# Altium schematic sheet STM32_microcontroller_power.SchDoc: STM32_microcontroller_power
size A4; Date: Not used; ApprovedBy: Not used; CheckedBy: Not used; Author: Not used; CompanyName: STMicroelectronics; DrawnBy: Not used; Engineer: Not used; Organization: Not used; Address1: Not used; Address2: Not used; Address3: Not used; Address4: Not used; DocumentNumber: Not used; Revision: Not used; SheetNumber: 4; SheetTotal: 12
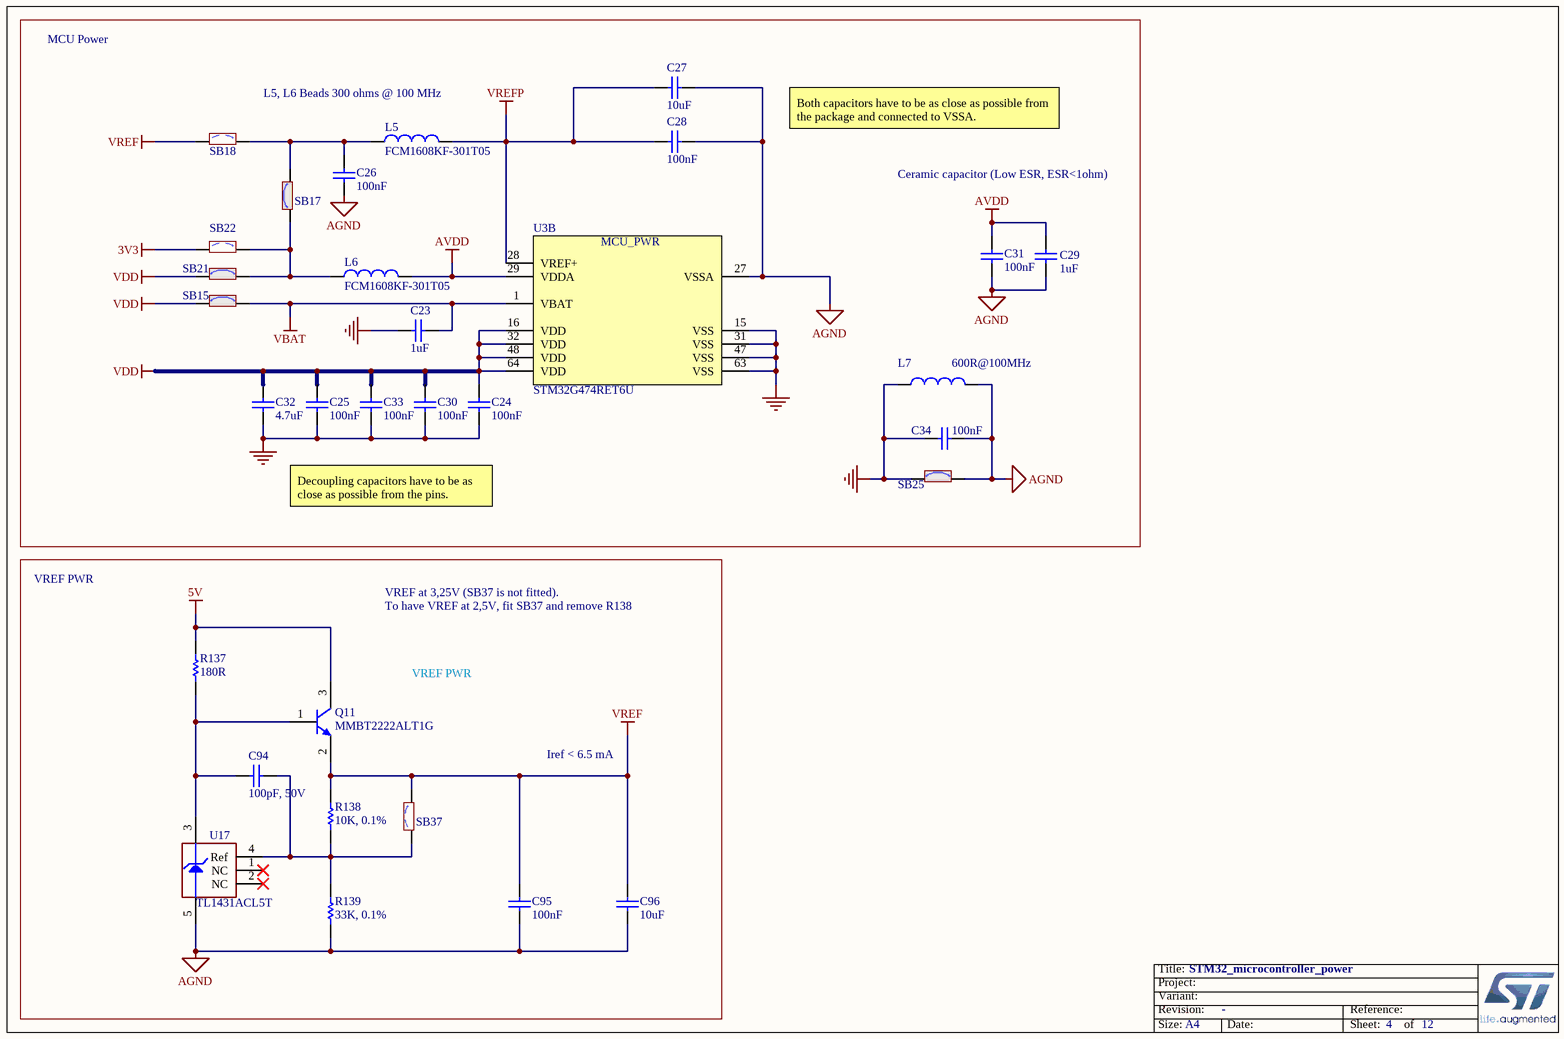
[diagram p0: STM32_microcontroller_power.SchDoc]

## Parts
C23  value 1uF  [C0603]
C24  value 100nF  [C0402]
C25  value 100nF  [C0402]
C26  value 100nF  [C0402]
C27  value 10uF  [C0603]
C28  value 100nF  [C0402]
C29  value 1uF  [C0603]
C30  value 100nF  [C0402]
C31  value 100nF  [C0402]
C32  value 4.7uF  [C0603]
C33  value 100nF  [C0402]
C34  value 100nF  [C0402]
C94  value 100pF, 50V  [C0603_H0P8]
C95  value 100nF  [C0603]
C96  value 10uF  [C0603]
L5  value FCM1608KF-301T05  [L0603]  (hidden comment: BEAD)
L6  value FCM1608KF-301T05  [L0603]  (hidden comment: BEAD)
L7  value 600R@100MHz  [L0603]
Q11  value MMBT2222ALT1G  [NPN_SOT23]  (hidden comment: 9013-SOT23)
R137  value 180R  [R0603]
R138  value 10K, 0.1%  [R0603]
R139  value 33K, 0.1%  [R0603]
SB15  (no value)  [SOLDER-BRIDGE_R0603-0R]
SB17  (no value)  [SOLDER-BRIDGE_R0603-0R]
SB18  (no value)  [SOLDER-BRIDGE_R0603-0R]
SB21  (no value)  [SOLDER-BRIDGE_R0603-0R]
SB22  (no value)  [SOLDER-BRIDGE_R0603-0R]
SB25  (no value)  [SOLDER-BRIDGE_R0603-0R]
SB37  (no value)  [SOLDER-BRIDGE_R0603-0R]
U3  STM32G474RET6U  [ICC_LQFP64_10X10_P050]  (part B of 2)
U17  value TL1431ACL5T  [ICC_SOT23-5L_H1P45]

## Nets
3V3: SB22.1
5V: Q11.3(C) R137.2
AGND: C26.1 C27.1 C28.2 C29.1 C31.1 C34.2 C95.1 C96.1 L7.2 R139.1 SB25.2 U3.27(VSSA) U17.5(Anode)
AVDD: C29.2 C31.2 L6.2 U3.29(VDDA)
GND: C23.1 C24.1 C25.1 C30.1 C32.1 C33.1 C34.1 L7.1 SB25.1 U3.15(VSS) U3.31(VSS) U3.47(VSS) U3.63(VSS)
VBAT: C23.2 SB15.2 U3.1(VBAT)
VDD: C24.2 C25.2 C30.2 C32.2 C33.2 SB15.1 SB21.1 U3.16(VDD) U3.32(VDD) U3.48(VDD) U3.64(VDD)
VREF: C95.2 C96.2 Q11.2(E) R138.2 SB18.1 SB37.2
VREFP: C27.2 C28.1 L5.2 U3.28(VREF+)
NetC26_2: C26.2 L5.1 SB17.2 SB18.2
NetC94_1: C94.1 Q11.1(B) R137.1 U17.3(Cathode)
NetC94_2: C94.2 R138.1 R139.2 SB37.1 U17.4(Ref)
NetL6_1: L6.1 SB17.1 SB21.2 SB22.2

Not connected (* = marked no-connect by the designer): U17 1(NC)* 2(NC)*

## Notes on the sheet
- MCU Power
- L5, L6 Beads 300 ohms @ 100 MHz
- Both capacitors have to be as close as possible from the package and connected to VSSA.
- Ceramic capacitor (Low ESR, ESR<1ohm)
- Decoupling capacitors have to be as close as possible from the pins.
- VREF PWR
- VREF at 3,25V (SB37 is not fitted).
- To have VREF at 2,5V, fit SB37 and remove R138
- Iref < 6.5 mA

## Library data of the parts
C23 C29 = MCD-00010: Capacitor, MLCC, 1uF, 16V, X5R, 10%, 0603, T=0,8mm; Manufacturer_Part_Number: CC0603KRX5R7BB105; Manufacturer: YAGEO; Provided_By: SUBCO
C24-C26 C28 C30 C31 C33 C34 = MCD-00102: Capacitor, MLCC, 100nF, 16V, X7R, 10%, 0402, T=0,5mm; Manufacturer_Part_Number: CC0402KRX7R7BB104; Manufacturer: YAGEO; Alternate_Manufacturer_Part_Number: GCM155R71C104KA55D; Alternate_Manufacturer: MURATA; Provided_By: SUBCO
C27 C96 = MCD-01124: Capacitor, MLCC, 10µF, 10V, X5R, 10%, 0603, T=0.8mm; Manufacturer_Part_Number: GRM188R61A106KAAL; Manufacturer: MURATA; Provided_By: SUBCO
C32 = MCD-00009: Capacitor, MLCC, 4.7uF, 16V, X5R, 10%, 0603, T=0.8mm; Manufacturer_Part_Number: CC0603KRX5R7BB475; Manufacturer: YAGEO; Provided_By: SUBCO
C94 = MCD-01648: Capacitor, MLCC, 100pF, 50V, NPO, 5%, 0603, T=0,8mm; Manufacturer_Part_Number: CC0603JRNPO9BN101; Manufacturer: YAGEO; Provided_By: SUBCO
C95 = MCD-00211: Capacitor, MLCC, 100nF, 16V, X7R, 10%, 0603, T=0,8mm; Manufacturer_Part_Number: CC0603KRX7R7BB104; Manufacturer: YAGEO; Provided_By: SUBCO
L5 L6 = MCD-01735: Bead,300R,500mA,0603; Part_Type: Inductor; Manufacturer: TAI-TECH; Provided_By: SUBCO
L7 = MCD-00047: SMD Chip ferrite bead, 600R@100MHz +/-25%, 350mA, 500mohm DC, 0603, T=0.8mm; Part_Type: Inductor; Manufacturer_Part_Number: FCM1608KF-601T03; Manufacturer: TAI-TECH; Provided_By: SUBCO
Q11 = MCD-01737: NPN Bipolar Transistor; Part_Type: IC; Manufacturer: ON SEMICONDUCTOR; Provided_By: SUBCO
R137 = MCD-00342: Resistor,180R,0603,1%,1/10W; Manufacturer_Part_Number: RC0603FR-07180RL; Manufacturer: YAGEO; Provided_By: SUBCO
R138 = MCD-01669: Resistor, 10K, 0603, 0.1%,1/10W; Manufacturer_Part_Number: ERA3AEB103V; Manufacturer: PANASONIC; Provided_By: SUBCO
R139 = MCD-01670: Resistor, 33K, 0603, 0.1%,1/10W; Manufacturer_Part_Number: ERA3AEB333V; Manufacturer: PANASONIC; Provided_By: SUBCO
SB15 SB17 SB21 SB25 = MCD-00071: Solder Bridge ON; Part_Type: Mechanical; Manufacturer_Part_Number: RC0603JR-070RL; Manufacturer: YAGEO; Provided_By: SUBCO
SB18 SB22 SB37 = MCD-00072: Solder Bridge OFF; Part_Type: Mechanical; Manufacturer_Part_Number: RC0603JR-070RL; Manufacturer: YAGEO; Provided_By: SUBCO
U3 = MCD-01584: STM32G474RET6U MCU, LQFP64 10x10, 1.6, 512KB Flash, 128KB SRAM; Part_Type: IC; Manufacturer: STMICROELECTRONICS; ECCN_US: 3A991A2; ECCN_EU: NEC; Provided_By: SUBCO with ST control
U17 = MCD-01157: Programmable voltage reference; Part_Type: IC; Manufacturer: STMICROELECTRONICS; Provided_By: SUBCO with ST control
